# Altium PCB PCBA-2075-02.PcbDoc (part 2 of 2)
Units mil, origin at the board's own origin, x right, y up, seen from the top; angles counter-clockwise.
Board outline 4700 x 3550 mil, 4 copper layers (Top Layer, Signal Layer 1, Signal Layer 2, Bottom Layer), stack 65.3 mil thick; 129 components, 149 nets, 748 pads, 314 vias.
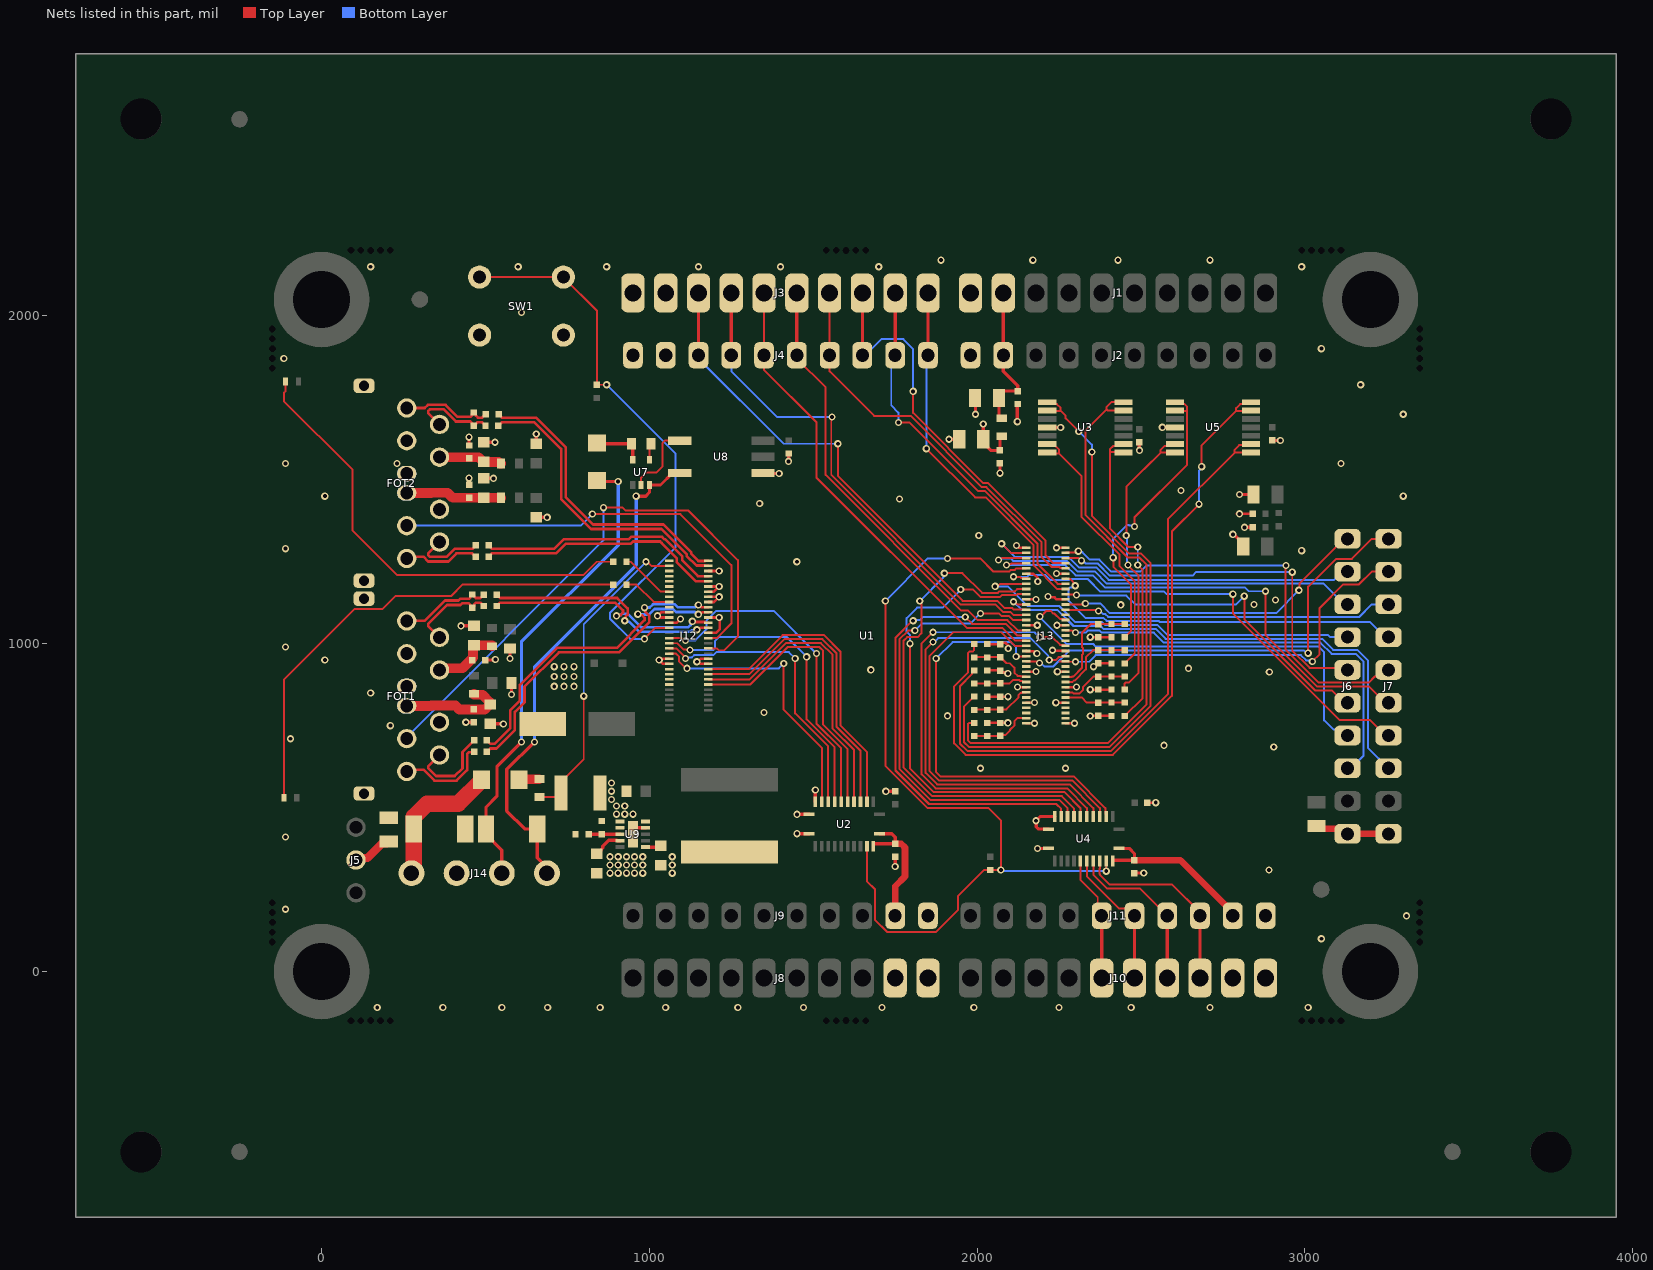
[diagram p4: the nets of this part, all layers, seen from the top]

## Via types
v1: diameter 22, hole 12, Top Layer to Bottom Layer, tented both sides, 314 vias

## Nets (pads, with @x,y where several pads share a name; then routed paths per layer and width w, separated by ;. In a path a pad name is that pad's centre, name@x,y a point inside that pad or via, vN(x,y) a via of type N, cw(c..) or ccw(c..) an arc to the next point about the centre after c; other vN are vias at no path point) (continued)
F5: J10.5 J11.5 U4.18 | length 394
  Top Layer w6: U4.18@2315.16,337.09 2315.16,279.84 2368,227 2368,206.09 2391.98,182.1 2392.1,182.1 J11.5@2380,170
  Top Layer w10: J10.5@2380,-20 J11.5@2380,170
F6: J10.6 J11.6 U4.19 | length 437.7
  Top Layer w6: U4.19@2334.84,337.09 2334.84,290.16 2433,192 2468,192 2480,180 J11.6@2480,170
  Top Layer w10: J10.6@2480,-20 J11.6@2480,170
F7: J10.7 J11.7 U4.20 | length 511.1
  Top Layer w6: U4.20@2354.53,337.09 2354.53,295.47 2397,253 2497,253 2550.41,199.59 2553.91,199.59 2580,173.51 J11.7@2580,170
  Top Layer w10: J10.7@2580,-20 J11.7@2580,170
F8: J10.8 J11.8 U4.21 | length 595.3
  Top Layer w6: U4.21@2374.21,337.09 2374.21,314.7 2373.9,314.39 2373.9,297.82 2374.21,297.5 2374.21,295.79 2405,265 2595,265 2680,180 J11.8@2680,170
  Top Layer w10: J10.8@2680,-20 J11.8@2680,170
GND: C1.1 C2.2 C3.2 C4.1 C5.2 C6.1 C7.2 C8.1 C9.1 C10.1 C11.1 C12.1 C13.1 C14.1 C15.1 C16.1 C17.2 C18.1 C19.1 C20.1 C21.1 C22.1 C23.1 C24.2 C27.1 C28.1 C29.- C30.2 C31.2 C34.1 C63.1 C64.1 C65.1 C68.1 C69.1 C70.2 C74.1 C75.1 C76.1 C79.1 C80.1 C81.2 FOT1.1 FOT1.4 FOT1.6 FOT1.8 FOT1.12 FOT2.1 FOT2.4 FOT2.6 FOT2.8 FOT2.12 J1.10 J2.10 J3.10 J4.10 J6.10 J7.10 J8.10 J9.10 J10.10 J11.10 J12.5 J12.11 J12.13 J12.15 J12.17 J12.22 J12.23 J12.24 J12.26 J12.29 J12.39 J12.40 J12.41 J12.42 J13.1 J13.2 J13.11 J13.12 J13.21 J13.22 J13.31 J13.32 J13.41 J13.42 J13.49 J13.50 J13.55 J13.56 J13.61 J13.62 J13.69 J13.70 J14.2 R2.1 R4.1 R6.1 R8.1 R11.1 R13.1 R15.1 R17.1 R21.2 SW1.2 TVS1.A U1.A1 U1.A2 U1.A11 U1.A12 U1.A21 U1.A22 U1.A31 U1.A32 U1.A41 U1.A42 U1.A49 U1.A50 U1.A55 U1.A56 U1.A61 U1.A62 U1.A69 U1.A70 U1.B5 U1.B11 U1.B13 U1.B15 U1.B17 U1.B22 U1.B23 U1.B24 U1.B26 U1.B29 U1.B39 U1.B40 U1.B41 U1.B42 U2.11 U2.12 U2.13 U3.11 U4.11 U4.12 U4.13 U5.11 U8.4 U9.1 U9.9 U9.11 | length 3187.2
  Top Layer w8: v1(1025,1085) 1028.13,1081.87 1031.01,1081.87 1032.76,1080.12 U1.B24@1060.35,1080.12 ; v1@1025.29,1085 1036.15,1095.87 U1.B22@1060.35,1095.87 ; U1.B42@1059.37,938.39 1041.61,938.39 v1(1030,950) 1033.79,950 1037.92,954.13 U1.B40@1059.37,954.13 ; U1.B26@1060.35,1064.37 1083.85,1064.37 1094.48,1075 v1(1095,1075) ; U1.B41@1179.65,938.39 1155.4,938.39 1148.79,945 1157.92,954.13 U1.B39@1179.65,954.13 ; U1.B29@1179.65,1032.87 1202.87,1032.87 1215,1045 1215,1078.27 v1(1213.15,1080.12) U1.B23@1180.63,1080.12 ; U1.B17@1180.63,1127.36 1196.8,1127.36 v1@1212.55,1143.11 ; U1.B15@1180.63,1143.11 v1@1212.55,1143.11 ; U1.B13@1180.63,1158.86 1196.8,1158.86 v1@1212.55,1174.61 ; U1.B11@1180.63,1174.61 v1@1212.55,1174.61 ; U1.B5@1180.63,1221.85 v1(1213.15,1221.85) ; v1(1213.15,1143.11) v1@1212.55,1143.11 ; v1(1213.15,1174.61) v1@1212.55,1174.61 ; R13.1@2030.63,758.56 v1(2093.56,758.56) ; R15.1@2030.63,838.39 v1(2094.14,838.39) ; R2.1@2030.63,918.56 2070.63,918.56 C10.1@2070.63,918.07 2076.47,912.23 2087.13,912.23 2089.92,909.44 v1(2093.71,909.44) ; R4.1@2030.63,998.56 2070.63,998.56 2074.84,1002.77 2086.7,1002.77 2095,994.47 v1(2095,985) ; v1(2069.69,1520.31) C2.2@2069.69,1550.31 ; v1(2120,1300) 2127.28,1292.72 U1.A2@2150.35,1292.72 ; v1(2123.3,867.52) U1.A56@2149.37,867.52 ; U1.A70@2149.37,757.28 v1(2175.44,757.28) ; U1.A62@2149.37,820.28 v1(2175.44,820.28) ; U1.A50@2149.37,914.76 v1@2175.44,914.76 ; U1.A42@2149.37,977.76 2150.12,977.01 2171.96,977.01 2178.97,970 v1(2182.22,970) ; U1.A32@2149.37,1056.5 2183.31,1056.5 v1(2183.46,1056.35) ; U1.A22@2150.35,1135.24 v1(2179.76,1135.24) ; U1.A12@2150.35,1213.98 2171.02,1213.98 2185,1200 v1(2185,1190) ; v1(2215.91,1144.09) 2218.59,1141.41 2236.74,1141.41 2242.91,1135.24 U1.A21@2270.63,1135.24 ; v1(2230,980) 2231.5,978.5 2269.88,978.5 U1.A41@2270.63,977.76 ; v1(2241.73,1292.72) U1.A1@2270.63,1292.72 ; v1(2242.27,1213.98) U1.A11@2270.63,1213.98 ; v1(2243.38,1056.37) 2243.5,1056.5 U1.A31@2270.63,1056.5 ; v1@2244.56,820.28 U1.A61@2270.63,820.28 ; v1(2244.56,914.76) U1.A49@2270.63,914.76 ; U1.A69@2270.63,757.28 v1(2296.7,757.28) ; U1.A55@2270.63,867.52 v1(2303.26,867.52) ; v1(2345.18,779.82) R11.1@2410,779.82 ; v1(2345.18,859.82) R8.1@2410,859.82 ; v1(2345.18,1019.82) R6.1@2410,1019.82 ; v1(2355,930) 2355,934.21 2355.26,934.47 2364.65,934.47 2370,939.82 R17.1@2410,939.82 ; C19.1@2519.69,515 v1(2545,515) ; v1@2792.08,1396.17 C7.2@2840.31,1396.17 ; v1(2800,1455) C6.1@2843.27,1455
  Top Layer w10: v1(425.47,1054.53) C64.1@465,1054.53 ; v1(440.31,760.31) C70.2@465,760.31 ; C81.2@450,1484.69 v1(450,1505) ; C76.1@450,1604.69 v1(450,1630) ; C80.1@495,1504.53 v1(524.53,1504.53) ; C75.1@495,1614.53 v1(529.53,1614.53) ; C65.1@499.68,950 530,950 530,952.1 v1(530.16,952.26) ; C69.1@515,755.47 v1(554.53,755.47) ; v1(575,955) C68.1@575,985.47 ; v1(579.53,845.47) C63.1@579.53,880 ; C79.1@655,1385.47 v1(688.52,1385.47) ; C74.1@655,1609.53 v1(655,1640) ; U9.11@950,418.73 950,427.67 960.75,438.42 U9.9@988.98,438.42 ; U8.4@1347.17,1520 1347.62,1519.55 1395.79,1519.55 v1(1396.24,1519.1) ; v1(1425,1556.36) C24.2@1425,1580.31 ; v1(1450.47,420.47) U2.13@1487.72,420.47 ; v1(1450.47,479.53) U2.12@1487.72,479.53 ; U2.11@1506.42,517.91 v1(1506.42,553.58) ; v1(1721.58,549.68) C14.1@1750,549.68 ; v1(1750,320) C15.1@1750,350.32 ; v1(1913.79,1623.79) C1.1@1945.87,1623.79 ; C8.1@1993.58,1750 1995,1748.58 v1(1995,1700) ; v1(2122.65,1677.35) 2122.65,1729.96 C9.1@2124,1731.31 ; v1(2184.53,375.47) U4.13@2217.72,375.47 ; U4.12@2217.72,434.53 2217.2,435.04 2185.86,435.04 2180,440.9 v1(2180,460) 2192.91,472.91 U4.11@2236.42,472.91 ; U3.11@2230,1660 2230.09,1659.91 2254.73,1659.91 v1@2254.82,1660 ; C20.1@2480,300.32 v1(2508.32,300.32) ; v1(2495,1590) C17.2@2495,1614.72 ; v1@2565.18,1660 2565.27,1660.09 2589.91,1660.09 U5.11@2590,1660 ; v1(2780,1333.61) 2782.3,1331.31 2786.32,1331.31 2812.17,1305.46 C4.1@2812.17,1296.61 ; v1(2816.06,1355) C5.2@2840.31,1355 ; C3.2@2900,1620.31 2900.16,1620.16 2924.84,1620.16 v1(2925,1620)
  Top Layer w20: C34.1@3035,443.58 3043.7,434.88 3115.12,434.88 J6.10@3130,420 J7.10@3255,420
  other v1: 170,-110 370,-110 550,-110 690,-110 850,-110 1050,-110 1270,-110 1470,-110 1710,-110 1990,-110 2250,-110 2470,-110 2710,-110 3010,-110 3050,100 3310,170 -110,190 880,300 905,300 930,300 955,300 980,300 1070,300 2890,310 880,325 905,325 930,325 955,325 980,325 1070,325 880,350 905,350 930,350 955,350 980,350 1070,350 -110,410 900,480 925,480 950,480 900,505 925,505 885,525 885,550 885,575 2010,620 2270,620 2905,685 2570,690 -94.68,710 210,750 1910,780 1350,790 2240,820 150,850 710,870 740,870 770,870 710,900 740,900 770,900 2891.31,913.75 2180,915 1675.73,920.35 2645,925 710,930 740,930 770,930 1145,945 10,950 -110,990 2438.17,1118.64 2845,1120 2910.14,1133.69 1450,1250 2990.19,1283.84 -110,1290 2005,1330 2800,1396.17 1336.61,1427.8 1762.97,1441.31 10,1450 3300,1450 2622.26,1467.26 -110,1550 230,1550 3110,1550 2255,1659.82 2565,1660.18 3300,1700 3170,1790 -115,1870 3050,1900 610,2010 150,2150 600,2150 870,2150 1150,2150 1400,2150 1700,2150 2990,2150 1890,2170 2170,2170 2430,2170 2710,2170
LED_B: J12.12 U1.B12
LED_G: J12.8 U1.B8
LED_R: J12.10 U1.B10
M_STOP: D2.A J14.3 TVS2.C | length 1452.3
  Top Layer w10: J14.3@560,300 550,310 550,370.51 501.85,418.66 TVS2.C@501.85,435 501.85,501.85 535,535 535,625 v1(610,700) ; D2.A@840,1497.91 842.91,1495 v1(905,1495)
  Bottom Layer w10: v1(610,700) 610,1005.56 905,1300.56 v1(905,1495)
M_STOP_RTN: J14.4 TVS2.A U7.3 U8.3 | length 1562.3
  Top Layer w10: v1(650,700) 648.38,700 565.5,617.12 565.5,489.5 620,435 TVS2.A@658.15,435 658.15,347.25 687.8,317.6 J14.4@687.8,300 ; v1(960,1450) 988.87,1450 1000.59,1461.72 U7.3@1000.59,1484.11 1034.11,1484.11 1070,1520 U8.3@1092.83,1520
  Bottom Layer w10: v1(650,700) 650,929.8 960,1239.8 v1(960,1450)
NetC30_1: C30.1 U9.4 | length 93.6
  Top Layer w10: C30.1@840,359.06 841.97,359.06 852.72,369.8 852.72,371.77 857.81,376.86 857.81,382.69 875.85,400.73 901.46,400.73 903.15,399.05 U9.4@911.02,399.05
NetC31_1: C31.1 U9.6 | length 57.8
  Top Layer w10: U9.6@988.98,379.36 1040.64,379.36 C31.1@1045,375
NetC64_2: C64.2 C65.2 FOT1.5 L2.2 | length 216.1
  Top Layer w30: FOT1.5@360,919.53 365.56,925.09 430.27,925.09 462.28,957.1 462.28,994.72 463.03,995.47 C64.2@465,995.47 519.25,995.47 520,994.72 L2.2@520,992.44
NetC69_2: C69.2 C70.1 FOT1.7 L3.2 | length 333.5
  Top Layer w30: FOT1.7@260,810.47 334.53,810.47 335.06,811 409,811 420.32,799.68 C70.1@465,799.68 498.19,799.68 C69.2@513.03,814.53 ; L3.2@465,847.44 465,845 465.75,844.25 490.75,844.25 512.28,822.72 512.28,815.28 C69.2@513.03,814.53 ; C69.2@515,814.53 C69.2@513.03,814.53
NetC75_2: C75.2 C76.2 FOT2.5 L4.2 | length 198.4
  Top Layer w30: FOT2.5@360,1569.06 363.74,1565.31 367.48,1569.06 479.45,1569.06 493.78,1554.72 540.28,1554.72 545,1550 L4.2@547.44,1550
NetC80_2: C80.2 C81.1 FOT2.7 L5.2 | length 294.1
  Top Layer w30: FOT2.7@260,1460 334.53,1460 335.06,1460.53 384.92,1460.53 400.13,1445.31 C81.1@450,1445.31 547.13,1445.31 L5.2@547.44,1445
NetD1_C: D1.C FB3.1 | length 62.7
  Top Layer w30: D1.C@602.09,585 603.37,586.28 603.72,586.28 FB3.1@664.25,586.28
NetD2_C: D2.C R18.2 U7.5 | length 157.1
  Top Layer w10: D2.C@840,1612.09 842.09,1610 R18.2@945.47,1610 949.41,1606.06 U7.5@949.41,1560.89
NetJ12_2: J12.2 U1.B2
NetJ12_6: J12.6 U1.B6
NetL1_1: L1.1 U9.10
NetLED1_C: LED1.C R25.2 | length 1484.8
  Top Layer w6: LED1.C@-114.68,530 -114.68,890.32 101.59,1106.59 186.59,1106.59 225,1145 395,1145 430,1180 R25.2@889.82,1180
NetLED2_C: LED2.C R23.2 | length 1411.5
  Top Layer w6: LED2.C@-109.68,1800 -109.68,1770.69 -115,1765.37 -115,1740 95,1530 95,1345 230,1210 800,1210 840,1250 R23.2@889.82,1250
NetR1_1: R1.1 U5.1 U5.2 | length 1894.5
  Top Layer w6: R1.1@1990.63,918.56 1990.14,918.56 1983.79,912.21 1983.79,906.82 1947.79,870.82 1947.79,695.19 1969.98,673 2409.04,673 2582,845.96 2582,1379.48 2785.75,1583.23 ; U5.1@2836.14,1583.23 2785.75,1583.23 ; U5.2@2836.14,1608.82 2832.87,1605.55 2799.58,1605.55 2785.75,1591.71 2785.75,1583.23
NetR3_1: R3.1 U5.6 U5.7 | length 2145.6
  Top Layer w6: R3.1@1990.63,998.56 1990.63,980.07 1987.12,976.56 1977.06,976.56 1971.79,971.29 1971.79,911.79 1930,870 1930,696.01 1965.01,661 2414.01,661 2594,840.99 2594,1342.36 v1(2677.23,1425.59) ; v1(2685,1540) 2685,1605 2790,1710 ; U5.6@2836.14,1711.18 2834.96,1710 2790,1710 ; U5.7@2836.14,1736.77 2830.28,1730.91 2802.43,1730.91 2790,1718.49 2790,1710
  Bottom Layer w6: v1(2677.23,1425.59) 2677.23,1528.44 2685,1536.21 v1(2685,1540)
NetR5_1: R5.1 U5.8 U5.9 | length 899.9
  Top Layer w6: v1(2415,1262.52) 2415.64,1261.88 2415.64,1234.36 2468.84,1181.16 2468.84,1038.17 2450.49,1019.82 R5.1@2450,1019.82 ; v1(2480,1358) 2480,1385 2640.42,1545.42 2640.42,1709.58 2640,1710 ; U5.9@2603.86,1711.18 2605.04,1710 2640,1710 ; U5.8@2627.41,1731.92 2628.42,1730.91 2633.27,1730.91 2640,1724.18 2640,1710
  Bottom Layer w6: v1(2415,1262.52) 2415,1320 2457,1362 2463,1362 2463.94,1361.06 2476.94,1361.06 v1(2480,1358)
NetR7_1: R7.1 U5.13 U5.14 | length 909.4
  Top Layer w6: R7.1@2450,859.82 2450,878.17 2453.65,881.83 2463.57,881.83 2492.84,911.1 2492.84,1207.16 v1(2460,1240) ; v1(2455,1330) 2455,1478.28 2509,1532.29 2509.06,1532.29 2560,1583.23 ; U5.14@2603.86,1583.23 2560,1583.23 ; U5.13@2603.86,1608.82 2598,1602.96 2571.25,1602.96 2560,1591.71 2560,1583.23
  Bottom Layer w6: v1(2455,1330) 2457.5,1327.5 2457.5,1242.5 v1(2460,1240)
NetR10_1: R10.1 U3.1 U3.2 | length 984
  Top Layer w6: U3.1@2446.14,1583.23 2444.37,1585 2405,1585 ; U3.2@2446.14,1608.82 2440.28,1602.96 2414.48,1602.96 2405,1593.49 2405,1585 ; R10.1@2450,779.82 2450.49,779.82 2504.84,834.17 2504.84,1225.16 2495,1235 v1(2490,1240) ; v1(2490,1295) 2461.72,1295 2405,1351.72 2405,1585
  Bottom Layer w6: v1(2490,1240) v1(2490,1295)
NetR12_1: R12.1 U3.6 U3.7 | length 1809.8
  Top Layer w6: R12.1@1990.63,758.56 1975.3,758.56 1971.79,755.05 1971.79,705.13 1979.92,697 2399.1,697 2516.84,814.74 2516.84,1241.44 2495.28,1263 2459.77,1263 2330,1392.77 2330,1649.7 2395,1714.7 ; U3.6@2446.14,1711.18 2398.51,1711.18 2395,1714.7 ; U3.7@2446.14,1736.77 2409.58,1736.77 2395,1722.19 2395,1714.7
NetR14_1: R14.1 U3.8 U3.9 | length 1912.2
  Top Layer w6: R14.1@1990.63,838.56 1990.14,838.56 1959.79,808.21 1959.79,700.16 1974.95,685 2404.07,685 2528.84,809.77 2528.84,1246.41 2500.25,1275 2464.75,1275 2350,1389.75 v1(2350,1585) ; U3.9@2213.86,1711.18 2215.04,1710 2255,1710 ; U3.8@2213.86,1736.77 2219.72,1730.91 2243.27,1730.91 2255,1719.18 2255,1710 ; v1(2310,1647.5) 2270,1687.5 2270,1695 2255,1710
  Bottom Layer w6: v1(2310,1647.5) 2350,1607.5 v1(2350,1585)
NetR16_1: R16.1 U3.13 U3.14 | length 841.1
  Top Layer w6: U3.14@2213.86,1583.23 2217.09,1580 2250,1580 ; U3.13@2213.86,1608.82 2232.56,1608.82 2250,1591.38 2250,1580 ; R16.1@2450,939.82 2450.49,939.82 2480.84,970.17 2480.84,1190.87 2435,1236.72 2435,1270.8 2318,1387.8 2318,1512 2250,1580
NetR18_1: R18.1 U7.4 | length 45.2
  Top Layer w6: U7.4@1000.59,1560.89 R18.1@1000.59,1606.06
NetR19_1: R19.1 R21.1 U9.3 | length 96
  Top Layer w10: R21.1@815.18,418.73 815.27,418.64 R19.1@850.16,418.64 ; R19.1@850.18,418.66 850.18,418.73 850.27,418.64 910.94,418.64 U9.3@911.02,418.73
NetU7_2: U7.2 U8.1 | length 229.3
  Top Layer w6: U7.2@975,1484.11 975,1506.6 990.9,1522.5 1022.5,1522.5 1040,1540 1040,1611.77 1048.23,1620 U8.1@1092.83,1620
NRST: J12.44 U1.B44
P1LED0: J12.14 R23.1 U1.B14 | length 166.9
  Top Layer w6: R23.1@930.18,1250 943.57,1250 1034.71,1158.86 U1.B14@1059.37,1158.86
P1LED1: J12.16 U1.B16
P2LED0: J12.18 R25.1 U1.B18 | length 151
  Top Layer w6: R25.1@930.18,1180 960.25,1180 1012.89,1127.36 U1.B18@1059.37,1127.36
P2LED1: J12.20 U1.B20
PA0_ADC123_CH0: C10.2 J13.54 R1.2 R2.2 U1.A54 | length 166.4
  Top Layer w6: R1.2@1990.63,878.21 R2.2@2030.63,878.21 2070.63,878.21 2098.21,878.21 2110,890 2127.88,890 2131.86,886.02 2136.84,886.02 2139.59,883.27 U1.A54@2149.37,883.27
PA3_ADC123_CH3: C11.2 J13.52 R3.2 R4.2 U1.A52 | length 191
  Top Layer w6: R3.2@1990.63,958.21 1992.42,960 2030.63,960 2061.11,960 C11.2@2066.52,954.59 ; C11.2@2070.63,958.7 2077.47,951.86 2078.14,951.86 2089.6,940.4 2099.98,940.4 2113.54,926.85 2113.54,912.07 2123.61,902 2132.85,902 2134.83,900.02 2148.37,900.02 U1.A52@2149.37,899.02
PA4_ADC12_CH4: C13.2 J13.51 R5.2 R6.2 U1.A51 | length 312
  Top Layer w6: U1.A51@2270.63,899.02 2289.5,899.02 2290.01,899.52 2293.16,899.52 2320,926.36 2320,965.8 2323.68,969.47 2323.68,986.04 2320,989.72 2320,1033.61 2346.56,1060.18 R6.2@2410,1060.18 R5.2@2450,1060.18
PA5_ADC12_CH5: C16.2 J13.57 R7.2 R8.2 U1.A57 | length 208.2
  Top Layer w6: U1.A57@2270.63,851.77 2290.73,851.77 2294.98,847.52 2311.55,847.52 2323.26,859.24 2323.26,868.26 2355.18,900.18 R8.2@2410,900.18 R7.2@2450,900.18
PA6_ADC12_CH6: C18.2 J13.59 R10.2 R11.2 U1.A59 | length 186.4
  Top Layer w6: U1.A59@2270.63,836.02 2289.5,836.02 2290.01,835.52 2316.52,835.52 2317.02,836.02 2318.98,836.02 2334.82,820.18 R11.2@2410,820.18 R10.2@2450,820.18
PB0: J13.40 U1.A40 U4.4 | length 1285.2
  Top Layer w6: U1.A40@2149.37,993.5 2114.78,993.5 2073.28,1035 1926.72,1035 1855,963.28 1855,611.06 1883.06,583 2290.02,583 2374.37,498.65 2374.37,473.07 U4.4@2374.21,472.91
PB1: J13.44 U1.A44 U4.3 | length 1261.3
  Top Layer w6: v1(1875,955) 1875,608.03 1888.03,595 2294.99,595 2391.39,498.6 2391.39,481.53 U4.3@2395,477.91 ; v1(2119.14,960.86) 2119.72,961.43 2148.8,961.43 U1.A44@2149.37,962.01
  Bottom Layer w6: v1(1875,955) 1925,1005 2103.28,1005 2119.14,989.14 v1(2119.14,960.86)
PB3: J12.46 U1.B46
PB9: J12.32 U1.B32 U2.7 | length 1043.3
  Top Layer w6: U1.B32@1059.37,1017.13 1098.54,1017.13 1105.67,1010 v1(1110,1010) ; v1(1510,970) 1510,756.31 1585.16,681.16 U2.7@1585.16,517.91
  Bottom Layer w6: v1(1110,1010) 1140.79,1010 1174.36,1043.57 1174.36,1069.61 1204.87,1100.12 1379.88,1100.12 v1(1510,970)
PC0_ADC123_CH10: C21.2 J13.68 R12.2 R13.2 U1.A68 | length 191.3
  Top Layer w6: R12.2@1990.63,718.21 R13.2@2030.63,718.21 2070.14,718.21 2072.89,720.96 2085.96,720.96 2100,735 2100,738.56 2101.85,738.56 2113.56,750.28 2113.56,763.56 2123.03,773.03 U1.A68@2149.37,773.03
PC2_ADC123_CH12: C22.2 J13.58 R14.2 R15.2 U1.A58 | length 184.8
  Top Layer w6: R14.2@1990.63,798.21 1992.42,800 2030.63,800 2070.63,800 2089.47,800 2126.59,837.12 2126.59,843.75 2131.86,849.02 2134.09,849.02 2135.84,850.77 2148.37,850.77 U1.A58@2149.37,851.77
PC3_ADC123_CH13: C23.2 J13.53 R16.2 R17.2 U1.A53 | length 241.1
  Top Layer w6: U1.A53@2270.63,883.27 2290.73,883.27 2294.98,887.52 2298.13,887.52 2332,921.39 2332,958.25 2353.92,980.18 R17.2@2410,980.18 R16.2@2450,980.18
PC6: J6.4 J13.16 U1.A16 | length 1238.1
  Top Layer w6: v1(2055,1175) 2059.97,1175 2061.65,1173.32 2070.8,1182.48 U1.A16@2149.37,1182.48
  Bottom Layer w6: v1(2055,1175) 2093.81,1175 2153.57,1115.24 2249.76,1115.24 2299,1066 2381.37,1066 2389.81,1057.57 2549.4,1057.57 2579.97,1027 3069.97,1027 3076.97,1020 J6.4@3130,1020
PC7_PA8: J6.5 J13.5 U1.A5 | length 1149.3
  Top Layer w6: U1.A5@2270.63,1261.22 2309.45,1261.22 2317.31,1253.36 v1(2318.36,1253.36) ; v1(2961.36,1218.13) 2961.36,978.84 3014.24,925.96 3124.04,925.96 J6.5@3130,920
  Bottom Layer w6: v1(2318.36,1253.36) 2322.69,1253.36 2331.31,1244.74 2368.14,1244.74 2404.88,1208 2657.47,1208 2667.61,1218.13 v1(2961.36,1218.13)
PC8_PB10: J7.7 J13.14 U1.A14 | length 1431.4
  Top Layer w6: v1(2110.69,1204.31) 2110.88,1204.12 2130.69,1204.12 2134.81,1200 J13.14@2154.02,1200 ; v1(2780,1151) 2780,1092.32 3105,767.33 3197.67,767.33 3245,720 J7.7@3255,720
  Bottom Layer w6: v1(2110.69,1204.31) 2152.55,1204.31 2158.24,1210 2207.93,1210 2223.95,1193.98 2279.72,1193.98 2282.49,1196.74 2338.26,1196.74 2376,1159 2570.28,1159 2578.28,1151 v1(2780,1151)
PC9_PA9: J7.4 J13.13 U1.A13 | length 1122.7
  Top Layer w6: U1.A13@2271.52,1199.11 2273.4,1197.23 2284.42,1197.23 2291.44,1190.21 2291.44,1189.07 2299.44,1181.07 v1(2299.44,1176.74)
  Bottom Layer w6: v1(2299.44,1176.74) 2295.11,1176.74 2289.33,1170.95 2283.24,1170.95 2279,1166.71 2279,1131 2331.99,1078.01 2386.33,1078.01 2394.78,1069.57 2554.38,1069.57 2557.94,1066 3199,1066 3245,1020 J7.4@3255,1020
PC13: J12.34 U1.B34 U2.8 | length 960.7
  Top Layer w6: U1.B34@1059.37,1001.38 1084.8,1001.38 1104.4,981.78 1123.39,981.78 v1(1124.4,980.76) ; v1(1480,960) 1480,769.34 1565.47,683.87 U2.8@1565.47,517.91
  Bottom Layer w6: v1(1124.4,980.76) 1194.52,980.76 1199.89,986.13 1199.89,1008.18 1211.72,1020 1420,1020 v1(1480,960)
PD0_PD6: J6.7 J13.29 U1.A29 | length 1310.8
  Top Layer w6: v1(2191.27,1083.24) 2194.94,1083.24 2211.7,1100 2224.12,1100 2232.11,1092.01 2236.11,1092.01 2253.12,1074.99 2267.88,1074.99 U1.A29@2270.63,1072.24
  Bottom Layer w6: v1(2191.27,1083.24) 2191.27,1080.2 2271.64,999.82 2353.46,999.82 2362.28,991 3042.28,991 3058.66,974.63 3058.66,766.34 3086.53,738.47 3111.53,738.47 J6.7@3130,720
PD1_PD5: J6.8 J13.33 U1.A33 | length 1304.4
  Top Layer w6: U1.A33@2270,1040.37 2270.63,1039.75 2289.92,1039.75 2295.67,1034 v1(2300,1034)
  Bottom Layer w6: v1(2300,1034) 2331.07,1034 2336.89,1039.82 2373.61,1039.82 2379.87,1033.57 2539.46,1033.57 2570.03,1003 3047.25,1003 3081.25,969 3154.94,969 3179,944.94 3179,659 3140,620 J6.8@3130,620
PD12_PB14: J6.1 J13.23 U1.A23 | length 977.5
  Top Layer w6: U1.A23@2270.37,1119.74 2327,1119.74 v1(2330,1122.74) ; v1(2981.36,1163) 2983,1164.64 2983,1183 3120,1320 J6.1@3130,1320
  Bottom Layer w6: v1(2330,1122.74) 2375.54,1122.74 2404.72,1093.57 2911.93,1093.57 v1(2981.36,1163)
PD13: J6.2 J13.4 U1.A4 | length 1196.9
  Top Layer w6: v1(2075,1305) 2103.03,1276.97 U1.A4@2149.37,1276.97
  Bottom Layer w6: v1(2075,1305) 2116,1264 2279.43,1264 2310.44,1232.99 2317.27,1232.99 2317.52,1232.74 2363.17,1232.74 2400.91,1195 3089.49,1195 3114.49,1220 J6.2@3130,1220
PD14: J6.3 J13.6 U1.A6 | length 1198.9
  Top Layer w6: 2075.55,1261.22 U1.A6@2149.37,1261.22
  Bottom Layer w6: v1(2065,1255) 2069.33,1255 2074.33,1260 2103.03,1260 2111.03,1252 2274.46,1252 2305.47,1220.99 2312.3,1220.99 2312.55,1220.74 2358.2,1220.74 2395.94,1183 3057,1183 3120,1120 J6.3@3130,1120
PD15: J13.10 R9.2 U1.A10 U2.22 U4.22 | length 2669.3
  Top Layer w6: U2.22@1663.9,382.09 1663.9,275.26 1689,250.16 1689,157.06 1725.06,121 1874.94,121 1941,187.06 1941,229.84 2021.16,310 R9.2@2039.33,310 ; v1(1720,1130) 1720,627.27 1848.27,499 2034.28,499 2072.2,461.08 v1(2072.2,310) 2040.18,310 R9.2@2040,309.82 ; v1(1910,1260) 2010,1260 2050,1220 2098.28,1220 2103.28,1225 2115,1225 2119.72,1229.72 U1.A10@2149.37,1229.72 ; v1(2393.9,306.1) U4.22@2393.9,337.09
  Bottom Layer w6: v1(1720,1130) 1850,1260 v1(1910,1260) ; v1(2072.2,310) 2076.1,306.1 v1(2393.9,306.1)
PE2: J12.45 U1.B45 U2.4 | length 936.1
  Top Layer w6: U1.B45@1180.63,906.89 1304.66,906.89 1411.77,1014 1528.23,1014 1571,971.23 1571,746.23 1644.21,673.01 U2.4@1644.21,517.91
PE3: J12.43 U1.B43 U2.3 | length 957.6
  Top Layer w6: U1.B43@1180.63,922.64 1303.44,922.64 1406.8,1026 1533.2,1026 1583,976.2 1583,751.2 1663.9,670.3 U2.3@1663.9,517.91
PE4: J12.47 U1.B47 U2.5 | length 914.6
  Top Layer w6: U1.B47@1180.63,891.14 1305.89,891.14 1416.75,1002 1523.25,1002 1559,966.25 1559,741.25 1624.53,675.73 U2.5@1624.53,517.91
PE7: J3.5 J4.5 J13.34 U1.A34 | length 1379.4
  Top Layer w6: J4.5@1450,1870 1537.59,1782.41 1537.59,1515.19 1951.66,1101.11 1972.85,1101.11 2001.72,1072.24 2092.61,1072.24 2124.1,1040.75 U1.A34@2149.37,1040.75
  Top Layer w10: J4.5@1450,1890 J3.5@1450,2070
PE8_PF11: J3.6 J4.6 J13.38 U1.A38 | length 1475
  Top Layer w6: J3.6@1350,2070 J4.6@1350,1880 1350.49,1879.51 1350.49,1834.51 1510,1675 1510,1506.72 1968.47,1048.24 2077.01,1048.24 2116,1009.25 U1.A38@2149.37,1009.25
PE9: J13.36 U1.A36 U4.10 | length 1429.4
  Top Layer w6: v1(1805,1070) 1802.77,1070 1751,1018.23 1751,613.24 1853.24,511 2241.05,511 2256.1,495.95 U4.10@2256.1,472.91 ; v1(1963.89,1081.11) 1984.76,1060.24 2087.64,1060.24 2122.88,1025 U1.A36@2149.37,1025
  Bottom Layer w6: v1(1805,1070) 1806.97,1071.97 1825,1071.97 1834.14,1081.11 v1(1963.89,1081.11)
PE10: J3.7 J4.7 J13.28 U1.A28 | length 1553.2
  Top Layer w6: v1(1557.59,1691.3) 1555,1688.72 1555,1514.75 1950.75,1119 2056.67,1119 2079.43,1096.24 2102.55,1096.24 2110.8,1087.99 U1.A28@2149.37,1087.99
  Top Layer w10: J4.7@1250,1880 J3.7@1250,2070
  Bottom Layer w6: J4.7@1250,1880 1250,1831 1389.7,1691.3 v1(1557.59,1691.3)
PE11: J13.30 U1.A30 U4.9 | length 1410.5
  Top Layer w6: v1(1810,1040) 1789.75,1040 1763,1013.25 1763,618.21 1858.21,523 2251.43,523 2275.79,498.65 U4.9@2275.79,472.91 ; v1(2010,1092.24) 2066.46,1092.24 2074.46,1084.24 2097.58,1084.24 2109.58,1072.24 U1.A30@2149.37,1072.24
  Bottom Layer w6: v1(1810,1040) 1831.11,1061.11 1978.87,1061.11 v1(2010,1092.24)
PE12: J7.8 J13.24 U1.A24 | length 1554.4
  Top Layer w6: v1(2110.83,1127.97) 2115.24,1127.97 2123.71,1119.49 U1.A24@2149.37,1119.49
  Bottom Layer w6: v1(2110.83,1127.97) 2135.57,1103.24 2244.79,1103.24 2294.03,1054 2376.4,1054 2384.84,1045.57 2544.43,1045.57 2575,1015 3052.23,1015 3086.23,981 3159.91,981 3192.01,948.9 3192.01,682.99 3225.41,649.59 3225.41,646.09 3251.49,620 J7.8@3255,620
PE13: J13.18 U1.A18 U4.8 | length 1542.6
  Top Layer w6: v1(1825,1130) 1825,1125.67 1830,1120.67 1830,1031.72 1818.28,1020 1786.72,1020 1775,1008.28 1775,623.18 1863.18,535 2258.28,535 2295.47,497.81 U4.8@2295.47,472.91 ; v1(1900,1215) 1955,1215 2015,1155 2063.28,1155 2068.25,1159.97 2114.97,1159.97 2121.73,1166.73 U1.A18@2149.37,1166.73
  Bottom Layer w6: v1(1825,1130) 1896.94,1201.94 1896.94,1211.94 v1(1900,1215)
PE14: J13.20 U1.A20 U4.7 | length 1471.4
  Top Layer w6: v1(1795,1000) 1795,620.15 1868.15,547 2266.96,547 2315.31,498.65 2315.31,473.07 U4.7@2315.16,472.91 ; v1(1950,1165) 1988.03,1165 2010.03,1143 2070.32,1143 2075.29,1147.97 2119.94,1147.97 2122.95,1150.98 U1.A20@2149.37,1150.98
  Bottom Layer w6: v1(1795,1000) 1795,1026.72 1785,1036.72 1785,1078.28 1816.72,1110 1895,1110 v1(1950,1165)
PF2: J12.49 U1.B49 U2.6 | length 896
  Top Layer w6: U1.B49@1180.63,875.39 1307.11,875.39 1421.72,990 1518.28,990 1530,978.28 1530,753.28 1605,678.28 U2.6@1605,515
PF6: J12.38 U1.B38 U2.10 | length 854.4
  Top Layer w6: U1.B38@1059.37,969.88 1081.39,969.88 1090,961.27 1090,946.72 1111.72,925 v1(1115,925) ; v1(1410,940) 1410,798.69 1526.42,682.28 1526.42,545.3 1526.1,544.98 U2.10@1526.1,517.91
  Bottom Layer w6: v1(1115,925) 1395,925 v1(1410,940)
PF7_ADC3_CH5: J13.67 U1.A67
PF8_ADC3_CH6: J13.60 U1.A60
PF9_ADC3_CH7: J13.65 U1.A65
PF10_ADC3_CH8: J13.63 U1.A63
PG9_PF0: J13.35 U1.A35
PG12: J13.37 U1.A37
PG13_PB4: J13.39 U1.A39 U4.6 | length 1442.8
  Top Layer w6: v1(1865,1035) 1831,1001 1831,601.12 1873.12,559 2274.49,559 2334.84,498.65 U4.6@2334.84,472.91 ; v1(2190,1020) 2209.37,1020 2229.37,1020 2253.12,996.25 2267.88,996.25 U1.A39@2270.63,993.5
  Bottom Layer w6: v1(1865,1035) 2175,1035 v1(2190,1020)
PG14_PB5: J13.43 U1.A43 U4.5 | length 1440.9
  Top Layer w6: v1(1865,1005) 1843,983 1843,606.09 1878.09,571 2282.17,571 2354.53,498.65 U4.5@2354.53,472.91 ; v1(2220,950) 2239.29,950 2248.55,959.26 2259.84,959.26 2264.58,964 2264.83,963.76 2268.88,963.76 U1.A43@2270.63,962.01
  Bottom Layer w6: v1(1865,1005) 1869.28,1005 1881.28,1017 2163.5,1017 2216.94,963.56 2216.94,953.06 v1(2220,950)
PG15: J12.36 U1.B36 U2.9 | length 886.7
  Top Layer w6: U1.B36@1059.37,985.63 1082.61,985.63 1110,958.24 v1(1110,955) ; v1(1445,955) 1445,787.37 1545.79,686.59 U2.9@1545.79,517.91
  Bottom Layer w6: v1@1116.94,958.06 1129.78,958.06 1136.72,965 1195.73,965 1204.87,974.13 1425.87,974.13 v1(1445,955)
PH4_PI7: J13.47 U1.A47
PH5_PF1: J13.48 U1.A48
PH6_PH12: J3.8 J4.8 J13.26 U1.A26 | length 1574.3
  Top Layer w6: v1(1575,1610) 1575,1511.72 1955.72,1131 2061.65,1131 2084.4,1108.24 2107.52,1108.24 2112.02,1103.74 U1.A26@2149.37,1103.74
  Top Layer w10: J4.8@1150,1880 J3.8@1150,2070
  Bottom Layer w6: J4.8@1150,1880 1150,1870 1410,1610 v1(1575,1610)
PH7_PH11: J7.3 J13.25 U1.A25 | length 1008.5
  Top Layer w6: U1.A25@2271.63,1102.74 2367.26,1102.74 v1(2370,1100)
  Bottom Layer w6: v1(2370,1100) 2374.33,1100 2384.31,1090.01 2391.3,1090.01 2399.75,1081.57 2559.35,1081.57 2559.91,1081 3164.94,1081 3203.94,1120 J7.3@3255,1120
PH8_PH10: J13.27 U1.A27
PH9_PB15: J7.6 J13.8 U1.A8 | length 1478.9
  Top Layer w6: v1(2090,1240) 2093.06,1243.06 2103.06,1243.06 2104.47,1244.47 2148.37,1244.47 U1.A8@2149.37,1245.47 ; v1(2880,1160) 2880,1026.26 3037.26,869 3196,869 3245,820 J7.6@3255,820
  Bottom Layer w6: v1(2090,1240) 2269.49,1240 2300.75,1208.74 2353.23,1208.74 2390.97,1171 2817.28,1171 2828.28,1160 v1(2880,1160)
PH13_PD3: J3.1 J4.1 J13.17 U1.A17 | length 1116.2
  Top Layer w6: v1(1845,1595) 1993.81,1446.19 2026.4,1446.19 2172.15,1300.44 2172.15,1238.84 2244.26,1166.73 U1.A17@2270.63,1166.73
  Top Layer w10: J4.1@1850,1880 J3.1@1850,2070
  Bottom Layer w6: v1(1845,1595) 1845,1875 J4.1@1850,1880
PH14_PA10: J3.4 J4.4 J13.9 U1.A9 | length 1225.1
  Top Layer w6: J3.4@1550,2070 1550,1831 1686,1695 1797.32,1695 2014.32,1478 2028.54,1478 2196.15,1310.39 2196.15,1265.64 2227.82,1233.98 2250.56,1233.98 2253.81,1230.72 2259.85,1230.72 J13.9@2260.85,1229.72
PH15_PD2: J3.2 J4.2 J13.15 U1.A15 | length 1169.7
  Top Layer w6: J4.2@1743,1873 J4.2@1750,1880 ; v1(1760,1675) 1793.28,1675 2002.28,1466 2023.56,1466 2184.15,1305.42 2184.15,1243.81 2245.48,1182.48 U1.A15@2270.63,1182.48
  Top Layer w10: J4.2@1750,1880 J3.2@1750,2070
  Bottom Layer w6: J4.2@1750,1880 1738,1868 1738,1727 1760,1705 v1(1760,1675)
PI1_PA11: J3.3 J4.3 J13.7 U1.A7 | length 1254.3
  Top Layer w6: v1(1805,1770) 1805,1704.29 2019.29,1490 2033.51,1490 2208.15,1315.36 2208.15,1270.62 2232.79,1245.98 2255.53,1245.98 2256.03,1245.47 U1.A7@2270.63,1245.47
  Top Layer w10: J4.3@1650,1880 J3.3@1650,2070
  Bottom Layer w6: J4.3@1650,1880 1667.91,1897.91 1677,1897.91 1708.09,1929 1774.94,1929 1805,1898.94 v1(1805,1770)
PI2_PA12: J7.5 J13.3 U1.A3 | length 1333.9
  Top Layer w6: U1.A3@2271.63,1277.97 2305.2,1277.97 2308.72,1281.48 v1(2308.72,1282.22) ; v1(2941.87,1238.23) 2941.36,1237.73 2941.36,981.87 3042.23,881 3194.41,881 3213.82,900.41 3235.41,900.41 J7.5@3255,920
  Bottom Layer w6: v1(2308.72,1282.22) 2311.78,1279.16 2320.84,1279.16 2343.26,1256.74 2373.11,1256.74 2409.85,1220 2498.28,1220 2516.52,1238.23 v1(2941.87,1238.23)
PI3: J6.6 J13.19 U1.A19 | length 1059.4
  Top Layer w6: U1.A19@2270.63,1150.98 2271.63,1149.98 2301.92,1149.98 v1(2302.94,1148.96) ; v1(2815,1145) 2815,1074.29 3032.29,857 3083,857 3120,820 J6.6@3130,820
  Bottom Layer w6: v1(2302.94,1148.96) 2304.9,1147 2455.28,1147 2483.28,1119 2789,1119 v1(2815,1145)
PI5_PE0: J7.1 J13.46 U1.A46 | length 1399.4
  Top Layer w6: U1.A46@2149.37,946.26 U1.A46@2150.35,946.26 2180.81,946.26 2186.07,941 v1(2190.4,941) ; v1(3010,971) 3010,1173.94 3095.06,1259 3142.94,1259 3203.94,1320 J7.1@3255,1320
  Bottom Layer w6: v1(2190.4,941) 2194.73,941 2205.73,930 2231.51,930 2280.51,979 2997.67,979 3005.67,971 v1(3010,971)
PI6_PE1: J7.2 J13.45 U1.A45 | length 1234.7
  Top Layer w6: 2251.26,945 v1(2300,945) ; 2251.89,945.63 2270,945.63 U1.A45@2270.63,946.26 ; v1(3022.53,945.96) 3045,968.43 3045,1108.94 3117.06,1181 3164.94,1181 3203.94,1220 J7.2@3255,1220
  Bottom Layer w6: v1(2300,945) 2341.72,945 2361.72,965 2987.72,965 3003.7,949.02 3019.47,949.02 v1(3022.53,945.96)
RESET: J12.28 R26.1 SW1.1 U1.B28 | length 1748.6
  Top Layer w6: SW1.1@482.05,2118.58 SW1.1@737.95,2118.58 840,2016.54 R26.1@840,1790.18 ; 850,1790 v1(870,1790) ; v1(985,1015) 1018.62,1048.62 U1.B28@1059.37,1048.62
  Bottom Layer w6: v1(870,1790) 1080,1580 1080,1294.75 880,1094.75 880,1076.72 941.72,1015 v1(985,1015)
RX1_N: C82.2 J12.7 U1.B7 | length 746.9
  Top Layer w8: C82.2@510,1300 520.5,1289.5 709.7,1289.5 739.02,1318.81 937.4,1318.81 944.43,1325.84 1038.59,1325.84 1045.97,1318.47 1048.79,1318.47 1100,1267.27 1100,1254.81 1148.46,1206.35 1180.38,1206.35 U1.B7@1180.63,1206.1
RX1_P: C78.2 J12.9 U1.B9 | length 748
  Top Layer w8: C78.2@509.69,1265 520.18,1275.5 715.5,1275.5 744.81,1304.81 943.2,1304.81 950.23,1311.84 1032.79,1311.84 1037.48,1307.16 1084,1260.64 1084,1248.19 1141.83,1190.35 U1.B9@1179.65,1190.35 U1.B9@1180.63,1190.35
RX1A_N: C82.1 FOT2.10 | length 215.6
  Top Layer w8: FOT2.10@360,1310 326.1,1276.1 326.1,1269.47 330.78,1264.78 381.27,1264.78 405.99,1289.5 460.13,1289.5 C82.1@470.63,1300
RX1A_P: C78.1 FOT2.11 | length 233.1
  Top Layer w8: FOT2.11@260,1260 265.34,1265.34 310.42,1265.34 324.98,1250.78 387.07,1250.78 411.79,1275.5 459.82,1275.5 C78.1@470.32,1265
RX2_N: C71.1 J12.21 U1.B21 | length 966.1
  Top Layer w8: C71.1@504.68,705 515.18,694.5 528.01,694.5 576,742.49 576,797.54 605.28,826.82 605.28,874.77 718.12,987.62 901.15,987.62 986,1072.47 986,1079.1 977.78,1087.32 967.68,1087.32 v1(965,1090) ; v1(1149.52,1089.74) 1153.5,1093.71 1159.06,1093.71 1161.21,1095.87 U1.B21@1179.65,1095.87
  Bottom Layer w8: v1(965,1090) 966,1089 999.3,1089 1016.3,1106 1072.24,1106 1081.5,1096.74 1138.74,1096.74 1145.74,1089.74 v1(1149.52,1089.74)
RX2_P: C67.1 J12.19 U1.B19 | length 977.6
  Top Layer w8: C67.1@504.68,670 515.18,680.5 533.81,680.5 590,736.69 590,791.74 619.28,821.02 619.28,868.97 723.92,973.62 906.95,973.62 1000,1066.67 1000,1084.9 987.68,1097.22 987.68,1107.32 v1(985,1110) ; v1(1149.52,1117.74) 1152.88,1117.74 1159,1111.61 U1.B19@1179.65,1111.61
  Bottom Layer w8: v1(985,1110) 985.51,1110.51 1001.01,1110.51 1010.5,1120 1078.03,1120 1087.29,1110.74 1138.74,1110.74 1145.74,1117.74 v1(1149.52,1117.74)
RX2A_N: C71.2 FOT1.10 | length 277.7
  Top Layer w8: FOT1.10@360,660.47 326.1,626.57 326.1,619.94 349.72,596.31 406.31,596.31 430,620 430,669.69 C71.2@465.31,705
RX2A_P: C67.2 FOT1.11 | length 286.7
  Top Layer w8: FOT1.11@260,610.47 265.34,615.82 310.42,615.82 343.92,582.31 412.11,582.31 444,614.2 444,663.63 448.69,668.32 463.63,668.32 C67.2@465.31,670
SD1: FOT2.9 J12.31 U1.B31 | length 1336.4
  Top Layer w6: v1(826.03,1395.59) 826.62,1395 1095,1395 1250,1240 1250,1061.62 1205.51,1017.13 U1.B31@1179.65,1017.13
  Bottom Layer w6: FOT2.9@260,1360 790.44,1360 v1(826.03,1395.59)
SD2: FOT1.9 J12.35 U1.B35 | length 1772.6
  Top Layer w6: v1(860,1415) 918.72,1415 926.72,1407 1118,1407 1270,1255 1270,1021.72 1228.28,980 1211.68,980 1206.05,985.63 U1.B35@1179.65,985.63
  Bottom Layer w6: FOT1.9@260,710.47 260,714.96 860,1314.96 v1(860,1415)
SWCLK: J12.50 U1.B50
SWDIO: J12.48 U1.B48
TX1_N: C77.2 J12.1 U1.B1 | length 917.6
  Top Layer w8: C77.2@540,1700 550.5,1689.5 655,1689.5 744.83,1599.66 744.83,1447.08 828.17,1363.75 1043.11,1363.75 1128,1278.87 1128,1274.06 1149.58,1252.47 1169.98,1252.47 1170.85,1253.35 U1.B1@1179.65,1253.35
TX1_P: C73.2 J12.3 U1.B3 | length 917.9
  Top Layer w8: C73.2@539.69,1665 550.18,1675.5 649.2,1675.5 730.83,1593.86 730.83,1441.28 822.37,1349.75 1037.32,1349.75 1114,1273.07 1114,1268.26 1143.78,1238.47 1169.98,1238.47 1170.85,1237.6 U1.B3@1179.65,1237.6
TX1A_N: C77.1 FOT2.2 R24.2 | length 280.3
  Top Layer w8: FOT2.2@260,1719.06 314.75,1719.06 324.47,1728.78 378.8,1728.78 415.58,1692 454.47,1692 459.16,1696.69 459.16,1699.83 464.51,1705.18 R24.2@465,1705.18 465.49,1705.18 470.84,1699.83 470.84,1695.96 477.3,1689.5 490.13,1689.5 C77.1@500.63,1700
TX1A_P: C73.1 FOT2.3 R24.1 | length 263.6
  Top Layer w8: FOT2.3@360,1669.06 325.59,1703.47 325.59,1710.1 330.27,1714.78 373,1714.78 409.78,1678 454.47,1678 459.16,1673.31 459.16,1670.17 464.51,1664.82 R24.1@465,1664.82 465.49,1664.82 470.84,1670.17 470.84,1670.81 475.53,1675.5 489.82,1675.5 C73.1@500.32,1665
TX2_N: C66.1 J12.27 U1.B27 | length 731.2
  Top Layer w8: C66.1@534.68,1150 545.18,1139.5 901.62,1139.5 933.82,1107.31 933.82,1089.08 927.68,1082.94 927.68,1072.68 v1(925,1070) ; v1(1145,1042.5) 1148.79,1042.5 1154.91,1048.62 U1.B27@1179.65,1048.62
  Bottom Layer w8: v1(925,1070) 927.68,1067.32 938.18,1067.32 968.87,1036.63 1125.14,1036.63 1129.74,1041.23 1143.74,1041.23 v1(1145,1042.5)
TX2_P: C62.1 J12.25 U1.B25 | length 741.2
  Top Layer w8: C62.1@534.68,1115 545.18,1125.5 895.83,1125.5 919.82,1101.51 919.82,1094.88 912.62,1087.68 902.68,1087.68 v1(900,1085) ; v1(1131.29,1068.38) 1133.55,1066.12 1169.1,1066.12 1170.85,1064.37 U1.B25@1179.65,1064.37
  Bottom Layer w8: v1(900,1085) 902.68,1087.68 912.98,1087.68 916.3,1091 934.3,1091 974.67,1050.63 1119.34,1050.63 1125.92,1057.22 1125.92,1059.23 1131.29,1064.59 v1(1131.29,1068.38)
TX2A_N: C66.2 FOT1.2 R20.2 | length 279.7
  Top Layer w8: FOT1.2@260,1069.53 314.75,1069.53 377.22,1132 418.04,1132 423.04,1137 449.47,1137 454.16,1141.69 454.16,1144.83 459.51,1150.18 460.49,1150.18 465.84,1144.83 465.84,1144.19 470.53,1139.5 484.81,1139.5 C66.2@495.31,1150
TX2A_P: C62.2 FOT1.3 R20.1 | length 271.5
  Top Layer w8: FOT1.3@360,1019.53 325.59,1053.94 325.59,1060.57 383.02,1118 423.84,1118 428.84,1123 449.47,1123 454.16,1118.31 454.16,1115.17 459.51,1109.82 460.49,1109.82 465.84,1115.17 465.84,1119.35 471.99,1125.5 484.81,1125.5 C62.2@495.31,1115
V+: C27.2 FB3.2 J12.4 R19.2 U1.B4 U9.2 | length 954.9
  Top Layer w6: FB3.2@665,532.44 722.44,532.44 C27.2@730,540 ; C27.2@730.94,545 730.94,578.46 800,647.52 v1(800,840) ; v1(990,1250) 993.48,1250 1005.88,1237.6 U1.B4@1059.37,1237.6
  Bottom Layer w6: v1(800,840) 800,1060 v1(990,1250)
V_IN: D1.A J14.1 TVS1.C | length 435.1
  Top Layer w50: J14.1@279.91,306.84 279.91,324.27 281.85,326.22 TVS1.C@281.85,451.34 ; TVS1.C@281.85,435 281.85,471.85 321.73,511.73 416.61,511.73 D1.A@488.5,583.62
V_REF: J13.66 U1.A66
VCC_A: C8.2 C9.2 FB2.2 J1.9 J2.9 | length 416.8
  Top Layer w10: FB2.2@2066.42,1696.72 C8.2@2066.42,1750 ; C8.2@2078,1770.69 C9.2@2124,1770.69 2124,1787 2080,1831 J2.9@2080,1880 J1.9@2080,2070
VCC_IO: C1.2 C2.1 C12.2 C15.2 C20.2 FB2.1 J3.9 J4.9 J5.2 J8.9 J9.9 J10.9 J11.9 U2.23 U2.24 U4.23 U4.24 | length 1207.2
  Top Layer w10: U2.23@1683.58,382.09 1683.58,389.17 1684.09,389.69 C15.2@1750,389.69 1750,410 1739.53,420.47 U2.24@1702.28,420.47 ; v1(2018.7,1670) C1.2@2018.7,1623.79 2018.7,1612.11 2041.13,1589.69 C2.1@2069.69,1589.69 2069.69,1627.3 FB2.1@2075,1632.62 ; U4.23@2413.58,337.09 2413.58,339.17 2414.09,339.69 C20.2@2480,339.69 2480,360 2464.53,375.47 U4.24@2432.28,375.47
  Top Layer w20: J9.9@1750,170 1750,260 1780,290 1780,377.97 1768.28,389.69 C15.2@1750,389.69 ; C20.2@2480,339.69 2620.31,339.69 2780,180 J11.9@2780,170
  Top Layer w25: J5.2@105,340 111.51,346.51 140.39,346.51 183.99,390.1 198.8,390.1 C12.2@205,396.3
VDDA: J13.64 U1.A64
pads on no net: FD1.F FD2.F FD3.F FD4.F FD5.F FD6.F FD7.F FD8.F FD9.F FD10.F ST1.1 ST2.1 ST3.1 ST4.1 TVS3.A TVS3.C U7.1 U9.7 U9.8

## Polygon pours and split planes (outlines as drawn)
3V3 on Signal Layer 2 "NO_THERMAL" (solid, remove dead copper, pour order 40): 835,1771.12 936.12,1670 1445,1670 1645,1470 2560,1470 2760,1270 2760,635 2565,440 649.03,440 649.03,390 -150,390 -150,2200 835,2200
VCC_IO on Signal Layer 2 "NO_THERMAL" (solid, remove dead copper, pour order 92): 3350,1782 3350,-149.53 -150,-149.53 -150,1782
3V3 on Signal Layer 2 "NO_THERMAL" (solid, remove dead copper, pour order 108): 825,1095 825,964.58 839.58,950 917.64,950 925,957.36 925,1070 900,1095
VCC_IO on Signal Layer 2 "PWR" (solid, remove dead copper, pour order 64): 833,2200 3350,2200 3350,1780 833,1780
GND on Signal Layer 1 "NO_THERMAL" (solid, remove dead copper, pour order 30): -150,-150 -149.53,1605 -150,2200 3350,2200 3350,-150
GND on Bottom Layer "gnd" (solid, remove dead copper, pour order 106): 3350,850 1410,850 1410,190 -150,190 -150,-150 3350,-150
GND on Bottom Layer "gnd" (solid, remove dead copper, pour order 105): -150,2200 -150,-150 750,-150 750,730 1410,730 1410,450 3350,450 3350,2200
5V on Bottom Layer "NO_THERMAL" (solid, remove dead copper, pour order 102): 1150.16,716.14 863.79,716.14 793.82,646.17 793.82,111.17 43.82,111.17 43.82,661.17 608.82,661.17 608.82,891.17 1148.96,891.17
GND on Bottom Layer "NO_THERMAL" (solid, pour order 98): 800,634.62 800,220 1385,220 1385,715 880.38,715
5VA on Bottom Layer "5V" (solid, remove dead copper, pour order 32): 2175,1800 2945,1800 2945,1490 2175,1490
GND on Top Layer "gnd" (solid, remove dead copper, pour order 107): -150,2200 -150,-150 1150,-150 1150,200 680,200 680,1000 1050,1000 1050,650 1150,650 1150,-150 3350,-150 3350,2200
GND on Top Layer "NO_THERMAL" (solid, remove dead copper, pour order 104): 800,600 800,850 890,850 890,1030 590.77,1030 590.77,600.77 590,600
3V3 on Top Layer "NO_THERMAL" (solid, remove dead copper, pour order 99): 1200,865 1280,865 1280,745 1200,745
NetL1_1 on Top Layer "NO_THERMAL" (solid, pour order 50): 975.31,448.73 975.31,488.73 1390,488.73 1390,373.73 1015.31,373.73 1015.31,448.73
5V on Top Layer "NO_THERMAL" (solid, remove dead copper, pour order 52): 900,970 1035,970 1035,835 1035,750 1400.15,750 1399.45,498.73 955.31,498.73 955,610 810,610 810,835 900,835
V+ on Top Layer "NO_THERMAL" (solid, pour order 60): 690,585 690,428.73 925.31,428.73 925.31,443.73 895.31,443.73 870.31,468.73 840.31,468.73 840.31,585
GND on Top Layer "NO_THERMAL" (solid, remove dead copper, pour order 62): 825.31,403.73 800.31,403.73 800.31,418.73 790.31,428.73 700,428.73 700,220 1130,220 1130,360 975.31,360 975.31,600 845.31,600 845.32,368.73 825.31,368.73

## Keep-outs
Keep-Out Layer:
  lines w10: -150,-0.33 -150,50 -150,2000 -150,2050.33 ; -150,0 ccw(c0,0) 0,-150 ; -150,230.87 -150,1819.13 ; -150,2050 cw(c0,2050) 0,2200 ; -0.33,-150 50,-150 3150,-150 3200.33,-150 ; -0.33,2200 50,2200 3150,2200 3200.33,2200 ; 230,-150 1519.13,-150 ; 230.87,2200 1520,2200 ; 1680,-150 2969.13,-150 2284.35,-150 ; 1680.87,2200 2970,2200 ; 3200,-150 ccw(c3200,0) 3350,0 ; 3200,2200 cw(c3200,2050) 3350,2050 ; 3350,-0.33 3350,50 3350,2000 3350,2050.33 ; 3350,230 3350,1820

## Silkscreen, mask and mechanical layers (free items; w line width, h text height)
Top Overlay:
  drawing of 19 lines, arcs and shapes, not listed
  text "RESET" at 830,1940 h40 r90
  text "B1 B2 B3 B4 B5 B6 B7 B8  +  -" at 1880,1820 h33 r180
  text "A1 A2 A3 A4 A5 A6 A7 A8  +  -" at 2900,1820 h33 r180
  text "C8 C7 C6 C5 C4 C3 C2 C1" at 2985,600 h33 r90
  text "D8 D7 D6 D5 D4 D3 D2 D1" at 3055,600 h33 r90
  text "3V3 5V" at -25,485 h50 r270
  text "PCBA-2075-02 REV A1" at 2712.77,390 h120 r90
  text "HEBI ROBOTICS" at 2795,390 h120 r90
  text "-   +" at 2985,385 h33 r90
  text "E1 E2 E3 E4 E5 E6 E7 E8  +  -" at 930,230 h33
  text "F1 F2 F3 F4 F5 F6 F7 F8  +  -" at 1950,230 h33
  text "V+ GND MS+ MS-" at 110,-205 h50
Bottom Overlay:
  lines w10: 850,1050 2950,1050 ; 1900,300 1900,1750
  text "B1  / B2 / B3 / B4 / B5 / B6 / B7 / B8 / VCC I/O / GND" at 910,1410 h57 r270
  text "A1 / A2 / A3 / A4 / A5 / A6 / A7 / A8 / VCC I/O / GND" at 1940,1410 h57 r270
  text "DIGITAL INPUTS" at 1360,1220 h57 r270
  text "ANALOG INPUTS" at 2390,1200 h57 r270
  text "PWM OUTPUTS" at 2200,470 h57 r270
  text "DIGITAL OUTPUTS" at 1170,450 h57 r270
  text "GND / VCC I/O / E8 / E7 / E6 / E5 / E4 / E3 / E2 / E1" at 910,230 h57 r270
  text "GND / VCC I/O / F8 / F7 / F6 / F5 / F4 / F3 / F2 / F1" at 1940,230 h57 r270
  text "Power:  / 12-48V DC" at 635,5 h50
Panel Outline:
  lines w5: -750,-750 3950,-750 ; -750,-750 3950,-750 ; -750,-750 -750,2800 ; -750,-750 -750,2800 ; -750,2800 3950,2800 ; -750,2800 3950,2800 ; 3950,-750 3950,2800 ; 3950,-750 3950,2800 ; -330,-280 ccw(c-280,-280) -280,-330 50,-330 ccw(c50,-280) 100,-280 100,-200 ccw(c50,-200) 50,-150 0,-150 cw(c0,0) -150,0 -150,50 ccw(c-200,50) -200,100 -280,100 ccw(c-280,50) -330,50 -330,-280 ; -330,250 ccw(c-280,250) -280,200 -200,200 ccw(c-200,250) -150,250 -150,1800 ccw(c-200,1800) -200,1850 -280,1850 ccw(c-280,1800) -330,1800 -330,250 ; -330,2000 ccw(c-280,2000) -280,1950 -200,1950 ccw(c-200,2000) -150,2000 -150,2050 cw(c0,2050) 0,2200 50,2200 ccw(c50,2250) 100,2250 100,2330 ccw(c50,2330) 50,2380 -280,2380 ccw(c-280,2330) -330,2330 -330,2000 ; 200,-280 ccw(c250,-280) 250,-330 1500,-330 ccw(c1500,-280) 1550,-280 1550,-200 ccw(c1500,-200) 1500,-150 250,-150 ccw(c250,-200) 200,-200 200,-280 ; 200,2250 ccw(c250,2250) 250,2200 1500,2200 ccw(c1500,2250) 1550,2250 1550,2330 ccw(c1500,2330) 1500,2380 250,2380 ccw(c250,2330) 200,2330 200,2250 ; 1650,-280 ccw(c1700,-280) 1700,-330 2950,-330 ccw(c2950,-280) 3000,-280 3000,-200 ccw(c2950,-200) 2950,-150 1700,-150 ccw(c1700,-200) 1650,-200 1650,-280 ; 1650,2250 ccw(c1700,2250) 1700,2200 2950,2200 ccw(c2950,2250) 3000,2250 3000,2330 ccw(c2950,2330) 2950,2380 1700,2380 ccw(c1700,2330) 1650,2330 1650,2250 ; 3100,-280 ccw(c3150,-280) 3150,-330 3480,-330 ccw(c3480,-280) 3530,-280 3530,50 ccw(c3480,50) 3480,100 3400,100 ccw(c3400,50) 3350,50 3350,0 cw(c3200,0) 3200,-150 3150,-150 ccw(c3150,-200) 3100,-200 3100,-280 ; 3100,2250 ccw(c3150,2250) 3150,2200 3200,2200 cw(c3200,2050) 3350,2050 3350,2000 ccw(c3400,2000) 3400,1950 3480,1950 ccw(c3480,2000) 3530,2000 3530,2330 ccw(c3480,2330) 3480,2380 3150,2380 ccw(c3150,2330) 3100,2330 3100,2250 ; 3350,250 ccw(c3400,250) 3400,200 3480,200 ccw(c3480,250) 3530,250 3530,1800 ccw(c3480,1800) 3480,1850 3400,1850 ccw(c3400,1800) 3350,1800 3350,250
Board Outline:
  lines w5: -150,-0.33 -150,50 -150,2000 -150,2050.33 ; -150,0 ccw(c0,0) 0,-150 ; -150,2050 cw(c0,2050) 0,2200 ; -0.33,-150 50,-150 3150,-150 3200.33,-150 ; -0.33,2200 50,2200 3150,2200 3200.33,2200 ; 3200,-150 ccw(c3200,0) 3350,0 ; 3200,2200 cw(c3200,2050) 3350,2050 ; 3350,-0.33 3350,50 3350,2000 3350,2050.33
